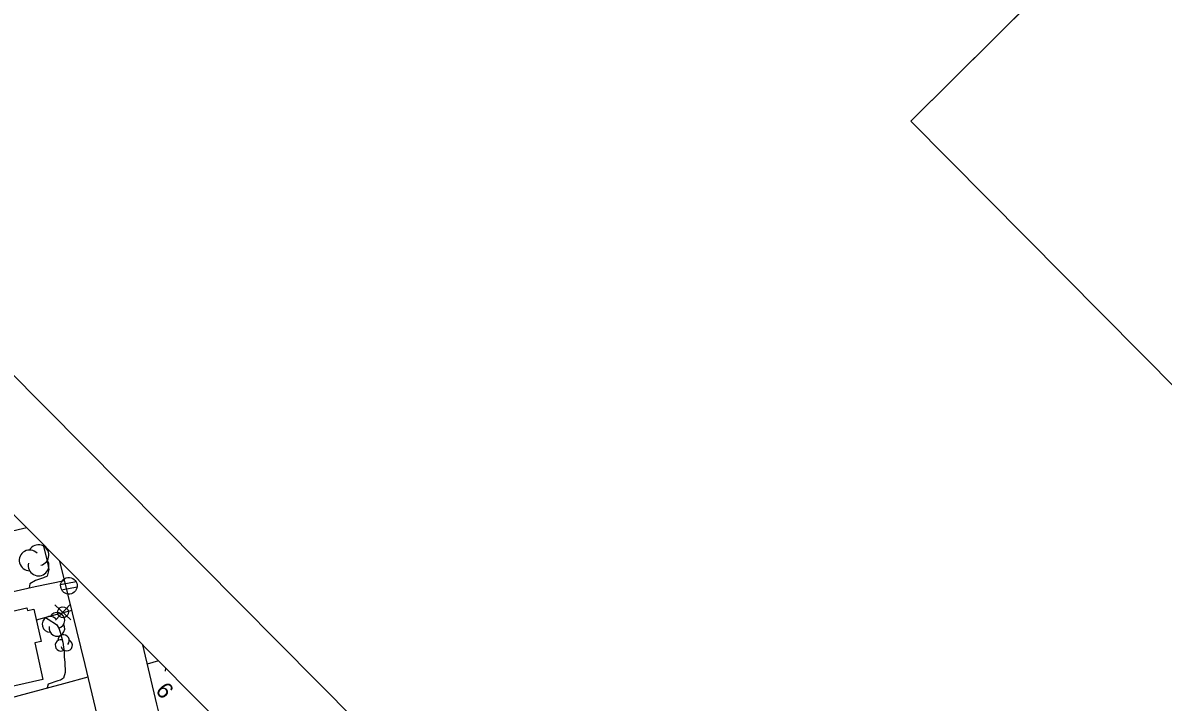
# Model space of a CAD drawing. Extents: x 381879 to 384696, y 5564785 to 5567594.
# Drawn here: x 383743.2 to 383952.8, y 5566849.1 to 5566973.9 of the extents above; entities that cross this region are included whole.
import ezdxf

# ---------------------------------------------------------------- set-up
doc = ezdxf.new("R2010")
doc.units = 0
for name, color, linetype in [('Niveau 19', 7, 'Continuous'), ('Niveau 2', 7, 'Continuous'), ('Niveau 21', 7, 'Continuous'), ('Niveau 31', 7, 'Continuous'), ('Niveau 36', 7, 'Continuous'), ('Niveau 44', 7, 'Continuous'), ('Niveau 60', 7, 'Continuous'), ('Niveau 63', 7, 'Continuous')]:
    doc.layers.add(name, color=color, linetype=linetype)

msp = doc.modelspace()

# ---------------------------------------------------------------- linework, layer by layer
at = {"layer": 'Niveau 19'}
for points in [[(383743.88, 5566881.12), (383740.46, 5566880.28)], [(383735.4, 5566868.06), (383745.46, 5566870.32), (383750.86, 5566871.42)], [(383752.21, 5566865.9), (383748.5, 5566864.9), (383745.65, 5566864.14)], [(383768.14, 5566856.66), (383766.02, 5566856.07)], [(383728.12, 5566846.05), (383728, 5566846.61), (383740.01, 5566849.62), (383750.71, 5566852.49), (383755.18, 5566853.7)]]:
    msp.add_lwpolyline(points, dxfattribs=at)
at = {"layer": 'Niveau 2'}
for points in [[(383746.84, 5566878.13), (383747.53, 5566875.51), (383747.93, 5566873.46), (383747.64, 5566872.22), (383746.97, 5566871.94), (383745.5, 5566871.4), (383744.49, 5566870.78), (383744.31, 5566870.06)], [(383747.36, 5566864.6), (383747.81, 5566864.34), (383749.36, 5566863.33), (383749.79, 5566862.67), (383750.02, 5566861.95), (383750.51, 5566860.11), (383750.78, 5566858.28), (383750.75, 5566857.36), (383750.89, 5566856.4), (383750.98, 5566854.5), (383750.63, 5566853.48), (383750.11, 5566853.13), (383749.59, 5566852.99), (383747.86, 5566852.38), (383747.64, 5566851.67)], [(383769.39, 5566854.75), (383769.48, 5566855.31)]]:
    msp.add_lwpolyline(points, dxfattribs=at)
at = {"layer": 'Niveau 21'}
for points in [[(383850.72, 5566624.73), (383846.58, 5566633.04), (383844.03, 5566638.18), (383837.03, 5566652.16), (383829.2, 5566667.73), (383821.17, 5566684.48), (383813.85, 5566699.66), (383805.07, 5566717.27), (383796.29, 5566734.96), (383792.97, 5566742.25), (383786.99, 5566757.71), (383780.6, 5566774.13), (383773.93, 5566791.44), (383765.36, 5566813.53), (383763.67, 5566818.84), (383759.05, 5566837.5), (383754.64, 5566855.96), (383750, 5566874.95)], [(383765.2, 5566859.63), (383767.73, 5566848.69), (383768.53, 5566845.49), (383769.74, 5566843.18), (383771.26, 5566841.85), (383773.64, 5566840.4), (383775.68, 5566839.95), (383777.13, 5566839.97), (383778.52, 5566840.03), (383783.07, 5566841.62)]]:
    msp.add_lwpolyline(points, dxfattribs=at)
at = {"layer": 'Niveau 31'}
msp.add_lwpolyline([(383738.39, 5566851.34), (383735.43, 5566864.46), (383743.92, 5566866.37), (383744.02, 5566865.9), (383745.19, 5566866.17), (383746.54, 5566860.21), (383745.35, 5566859.95), (383746.87, 5566853.25)], close=True, dxfattribs=at)
at = {"layer": 'Niveau 36'}
for p, q in [((383752.95, 5566871.18), (383750.11, 5566870.6)), ((383750.31, 5566869.7), (383753.15, 5566870.28)), ((383749.08, 5566866.93), (383752, 5566864.21)), ((383749.18, 5566864.11), (383751.9, 5566867.03))]:
    msp.add_line(p, q, dxfattribs=at)
for centre, major_axis in [((383751.64, 5566870.44), (-0.18, 1.51)), ((383750.55, 5566865.57), (0.116, -0.993))]:
    msp.add_ellipse(centre, major_axis=major_axis, ratio=0.99999, dxfattribs=at)
at = {"layer": 'Niveau 44'}
for centre, radius, start, end in [((383744.42, 5566875.12), 1.9, 44.1153, 269.8039), ((383746.06, 5566876.08), 1.9, 282.2692, 149.7262), ((383746.06, 5566874.17), 1.9, 166.9368, 29.6212), ((383748.18, 5566863.37), 1.45, 44.1153, 269.8039), ((383749.43, 5566864.09), 1.45, 282.2692, 149.7262), ((383749.43, 5566862.64), 1.45, 166.9368, 29.6212)]:
    msp.add_arc(centre, radius, start, end, dxfattribs=at)
for centre, start_param, end_param in [((383750.18, 5566859.49), 2.834597, 6.721173), ((383750.67, 5566860.41), 0.690957, 4.629966), ((383751.23, 5566859.53), 4.847526, 8.817401)]:
    msp.add_ellipse(centre, major_axis=(0.12, -1.04), ratio=0.99999, start_param=start_param, end_param=end_param, dxfattribs=at)
at = {"layer": 'Niveau 60'}
for points in [[(383794.43, 5567565.69), (383439.46, 5567213.56), (384312.69, 5566333.28), (384667.66, 5566685.41)], [(383653.8, 5566971.92), (383426.67, 5567200.87), (383197.47, 5566973.49), (381907.4, 5565693.71), (382780.65, 5564813.45), (384299.92, 5566320.61)]]:
    msp.add_lwpolyline(points, close=True, dxfattribs=at)
at = {"layer": 'Niveau 63'}
msp.add_lwpolyline([(384012.04, 5566849.33), (384154.03, 5566990.18), (384048.39, 5567096.67), (383906.4, 5566955.82)], close=True, dxfattribs=at)
msp.add_lwpolyline([(384108.05, 5566944.57), (384012.04, 5566849.33), (383906.4, 5566955.82), (383966.71, 5567015.65)], dxfattribs=at)

# ---------------------------------------------------------------- texts
at = {"layer": 'Niveau 2'}
msp.add_text('6', height=3, rotation=310.0643, dxfattribs=at).set_placement((383767.41, 5566851.13))

doc.saveas('drawing.dxf')
